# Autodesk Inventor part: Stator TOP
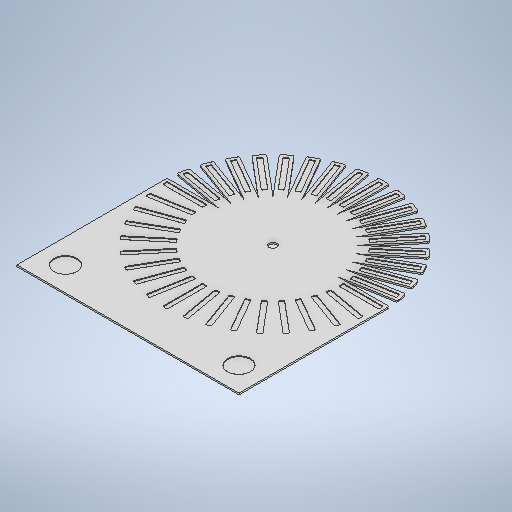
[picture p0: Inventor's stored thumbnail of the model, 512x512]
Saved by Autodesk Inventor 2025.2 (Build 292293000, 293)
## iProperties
Created: 2025-04
Part Number: Stator TOP
Material: Generic
Document SubType Name: Modeling
Designer: bensa
Density: 1 g/cm^3
Appearance: Default
Author: bensa
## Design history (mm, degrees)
sketch "Sketch1"
  geometry: L1 (-143.5, 6.85)-(143.5, 6.85); L2 (145.5, 4.85)-(145.5, -4.85); L3 (143.5, -6.85)-(-143.5, -6.85); L4 (-145.5, -4.85)-(-145.5, 4.85); L5 (-143.406, 6.751)-(145.5, -6.85); L6 (145.5, 6.85)-(-145.5, -6.85); L7 (-6.85, 143.5)-(-6.85, -143.5); L8 (-4.85, -145.5)-(4.85, -145.5); L9 (6.85, -143.5)-(6.85, 143.5); L10 (4.85, 145.5)-(-4.85, 145.5); L11 (-6.85, 145.5)-(6.85, -145.5); L12 (-6.85, -145.5)-(6.85, 145.5); L13 (-140.13, 31.664)-(142.509, -18.173); L14 (144.132, -20.489)-(142.447, -30.042); L15 (140.13, -31.664)-(-142.509, 18.173); L16 (-144.132, 20.489)-(-142.447, 30.042); L17 (-142.1, 32.012)-(142.1, -32.012); L18 (144.479, -18.52)-(-144.479, 18.52); L19 (-142.1, 32.012)-(144.9, 32.012); L20 (-137.189, 42.643)-(132.503, -55.517); L21 (135.066, -54.321)-(138.384, -45.206); L22 (137.189, -42.643)-(-132.503, 55.517); L23 (-135.066, 54.321)-(-138.384, 45.206); L24 (-139.068, 43.327)-(139.068, -43.327); L25 (134.382, -56.201)-(-134.382, 56.201); L26 (-139.068, 43.327)-(147.932, 43.327); L27 (-127.7, 65.818)-(120.85, -77.682); L28 (123.582, -76.95)-(128.432, -68.55); L29 (127.7, -65.818)-(-120.85, 77.682); L30 (-123.582, 76.95)-(-128.432, 68.55); L31 (-129.432, 66.818)-(129.432, -66.818); L32 (122.582, -78.682)-(-120.817, 77.55); L33 (-114.33, 86.993)-(105.524, -97.487); L34 (108.342, -97.241)-(114.577, -89.81); L35 (114.33, -86.993)-(-105.524, 97.487); L36 (-108.342, 97.241)-(-114.577, 89.81); L37 (-115.863, 88.278)-(115.863, -88.278); L38 (107.056, -98.773)-(-105.516, 97.351); L39 (-97.487, 105.524)-(86.993, -114.33); L40 (89.81, -114.577)-(97.241, -108.342); L41 (97.487, -105.524)-(-86.993, 114.33); L42 (-89.81, 114.577)-(-97.241, 108.342); L43 (-98.773, 107.056)-(98.773, -107.056); L44 (87.008, -114.195)-(-88.278, 115.863); L45 (-77.682, 120.85)-(65.818, -127.7); L46 (68.55, -128.432)-(76.95, -123.582); L47 (77.682, -120.85)-(-65.818, 127.7); L48 (-68.55, 128.432)-(-76.95, 123.582); L49 (-78.682, 122.582)-(78.682, -122.582); L50 (66.818, -129.432)-(-66.818, 129.432); L51 (-55.517, 132.503)-(42.643, -137.189); L52 (45.206, -138.384)-(54.321, -135.066); L53 (55.517, -132.503)-(-42.643, 137.189); L54 (-45.206, 138.384)-(-54.321, 135.066); L55 (-56.201, 134.382)-(56.201, -134.382); L56 (43.327, -139.068)-(-43.327, 139.068); L57 (-31.664, 140.13)-(18.173, -142.509); L58 (20.489, -144.132)-(30.042, -142.447); L59 (31.664, -140.13)-(-18.173, 142.509); L60 (-20.489, 144.132)-(-30.042, 142.447); L61 (-32.012, 142.1)-(32.012, -142.1); L62 (18.52, -144.479)-(-18.52, 144.479); L63 (18.173, 142.509)-(-31.664, -140.13); L64 (-30.042, -142.447)-(-20.489, -144.132)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; A1 r 2 centre (113.045, 88.525) between (114.33, 86.993) and (114.577, 89.81); A2 r 2 centre (121.85, 75.95) between (123.582, 76.95) and (120.85, 77.682); A3 r 2 centre (126.7, 67.55) between (127.7, 65.818) and (128.432, 68.55); A4 r 2 centre (133.187, 53.637) between (135.066, 54.321) and (132.503, 55.517); A5 r 2 centre (136.505, 44.522) between (137.189, 42.643) and (138.384, 45.206); A6 r 2 centre (140.478, 29.695) between (142.447, 30.042) and (140.13, 31.664); A7 r 2 centre (142.162, 20.142) between (142.509, 18.173) and (144.132, 20.489); A8 r 2 centre (143.5, 4.85) between (145.5, 4.85) and (143.5, 6.85); A9 r 2 centre (143.5, -4.85) between (143.5, -6.85) and (145.5, -4.85); A10 r 2 centre (142.162, -20.142) between (144.132, -20.489) and (142.509, -18.173); A11 r 2 centre (140.478, -29.695) between (140.13, -31.664) and (142.447, -30.042); A12 r 2 centre (136.505, -44.522) between (138.384, -45.206) and (137.189, -42.643); A13 r 2 centre (133.187, -53.637) between (132.503, -55.517) and (135.066, -54.321); A14 r 2 centre (126.7, -67.55) between (128.432, -68.55) and (127.7, -65.818); A15 r 2 centre (121.85, -75.95) between (120.85, -77.682) and (123.582, -76.95); A16 r 2 centre (113.045, -88.525) between (114.577, -89.81) and (114.33, -86.993); A17 r 2 centre (106.81, -95.955) between (105.524, -97.487) and (108.342, -97.241); A18 r 2 centre (95.955, -106.81) between (97.241, -108.342) and (97.487, -105.524); A19 r 2 centre (75.95, -121.85) between (76.95, -123.582) and (77.682, -120.85); A20 r 2 centre (67.55, -126.7) between (65.818, -127.7) and (68.55, -128.432); A21 r 2 centre (53.637, -133.187) between (54.321, -135.066) and (55.517, -132.503); A22 r 2 centre (44.522, -136.505) between (42.643, -137.189) and (45.206, -138.384); A23 r 2 centre (29.695, -140.478) between (30.042, -142.447) and (31.664, -140.13); A24 r 2 centre (20.142, -142.162) between (18.173, -142.509) and (20.489, -144.132); A25 r 2 centre (4.85, -143.5) between (4.85, -145.5) and (6.85, -143.5); A26 r 2 centre (-4.85, -143.5) between (-6.85, -143.5) and (-4.85, -145.5); A27 r 2 centre (-20.142, -142.162) between (-20.489, -144.132) and (-18.173, -142.509); A28 r 2 centre (-29.695, -140.478) between (-31.664, -140.13) and (-30.042, -142.447); A29 r 2 centre (-44.522, -136.505) between (-45.206, -138.384) and (-42.643, -137.189); A30 r 2 centre (-53.637, -133.187) between (-55.517, -132.503) and (-54.321, -135.066); A31 r 2 centre (-67.55, -126.7) between (-68.55, -128.432) and (-65.818, -127.7); A32 r 2 centre (-75.95, -121.85) between (-77.682, -120.85) and (-76.95, -123.582); A33 r 2 centre (-88.525, -113.045) between (-89.81, -114.577) and (-86.993, -114.33); A34 r 2 centre (-95.955, -106.81) between (-97.487, -105.524) and (-97.241, -108.342); A35 r 2 centre (-106.81, -95.955) between (-108.342, -97.241) and (-105.524, -97.487); A36 r 2 centre (-113.045, -88.525) between (-114.33, -86.993) and (-114.577, -89.81); A37 r 2 centre (-121.85, -75.95) between (-123.582, -76.95) and (-120.85, -77.682); A38 r 2 centre (-126.7, -67.55) between (-127.7, -65.818) and (-128.432, -68.55); A39 r 2 centre (-136.505, -44.522) between (-137.189, -42.643) and (-138.384, -45.206); A40 r 2 centre (-140.478, -29.695) between (-142.447, -30.042) and (-140.13, -31.664); A41 r 2 centre (-142.162, -20.142) between (-142.509, -18.173) and (-144.132, -20.489); A42 r 2 centre (-143.5, -4.85) between (-145.5, -4.85) and (-143.5, -6.85); A43 r 2 centre (-142.162, 20.142) between (-144.132, 20.489) and (-142.509, 18.173); A44 r 2 centre (-140.478, 29.695) between (-140.13, 31.664) and (-142.447, 30.042); A45 r 2 centre (-136.505, 44.522) between (-138.384, 45.206) and (-137.189, 42.643); A46 r 2 centre (-133.187, 53.637) between (-132.503, 55.517) and (-135.066, 54.321); A47 r 2 centre (-126.7, 67.55) between (-128.432, 68.55) and (-127.7, 65.818); A48 r 2 centre (-113.045, 88.525) between (-114.577, 89.81) and (-114.33, 86.993); A49 r 2 centre (-95.955, 106.81) between (-97.241, 108.342) and (-97.487, 105.524); A50 r 2 centre (-88.525, 113.045) between (-86.993, 114.33) and (-89.81, 114.577); A51 r 2 centre (-75.95, 121.85) between (-76.95, 123.582) and (-77.682, 120.85); A52 r 2 centre (-67.55, 126.7) between (-65.818, 127.7) and (-68.55, 128.432); A53 r 2 centre (-53.637, 133.187) between (-54.321, 135.066) and (-55.517, 132.503); A54 r 2 centre (-44.522, 136.505) between (-42.643, 137.189) and (-45.206, 138.384); A55 r 2 centre (-29.695, 140.478) between (-30.042, 142.447) and (-31.664, 140.13); A56 r 2 centre (-20.142, 142.162) between (-18.173, 142.509) and (-20.489, 144.132); A57 r 2 centre (-4.85, 143.5) between (-4.85, 145.5) and (-6.85, 143.5); A58 r 2 centre (4.85, 143.5) between (6.85, 143.5) and (4.85, 145.5); A59 r 2 centre (20.142, 142.162) between (20.489, 144.132) and (18.173, 142.509); A60 r 2 centre (29.695, 140.478) between (31.664, 140.13) and (30.042, 142.447); A61 r 2 centre (44.522, 136.505) between (45.206, 138.384) and (42.643, 137.189); A62 r 2 centre (53.637, 133.187) between (55.517, 132.503) and (54.321, 135.066); A63 r 2 centre (67.55, 126.7) between (68.55, 128.432) and (65.818, 127.7); A64 r 2 centre (75.95, 121.85) between (77.682, 120.85) and (76.95, 123.582)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; 45 further points
  constraints: 220 end point, 158 point on line, 144 point on circle, 144 tangent, 72 centre point, 36 equal radius, 36 parallel, 31 midpoint, 19 perpendicular, 3 horizontal, 2 equal length, 1 vertical
  dimensions: "d1" = 13.7 distance of L6.start L5.end; "d52" = 2 radius of A9 (derived); "d53" = 2 radius of A23 (derived); "d54" = 2 radius of A60 (derived); "d58" = 2 radius of A66 (derived); "d59" = 2 radius of A67 (derived); "d60" = 2 radius of A68 (derived); "d61" = 2 radius of A69 (derived); "d62" = 2 radius of A70 (derived); "d63" = 2 radius of A71 (derived); "d64" = 2 radius of A72 (derived)
sketch "Sketch2"
  geometry: L1 (-145.5, 190)-(-145.5, 0); L2 (-145.5, 0)-(145.5, 0); L3 (145.5, 0)-(145.5, 190); L4 (145.5, 190)-(-145.5, 190); L5 (-145.5, 190)-(145.5, 0); L6 (-145.5, 0)-(145.5, 190); 2 further points
  constraints: 12 end point, 2 midpoint, 2 parallel, 1 perpendicular
extrude "Extrusion1" new body sketch "Sketch1" distance "d65" = 2; taper "d66" = 0 deg
sketch "Sketch4"
  geometry: L1 (142.509, -18.173)-(78.296, -6.85) reference; L2 (64.381, -45.08)-(114.33, -86.993) reference; L3 (42.643, -137.189)-(20.342, -75.917) reference; L4 (18.173, 142.509)-(6.85, 78.296) reference; L5 (2, 141.65)-(-2, 141.65); L6 (31.664, 140.13)-(20.342, 75.917) reference; L7 (45.628, 134.134)-(50.327, 132.423); L8 (20.342, 75.917)-(42.643, 137.189) reference; L9 (68.857, 123.808)-(73.188, 121.308); L10 (-72.557, 121.672)-(-69.093, 123.672); L11 (-65.818, 127.7)-(-33.216, 71.231) reference; L12 (-50.327, 132.423)-(-46.568, 133.792); L13 (-42.643, 137.189)-(-20.342, 75.917) reference; L14 (-26.567, 139.151)-(-22.628, 139.845); L15 (-18.173, 142.509)-(-6.85, 78.296) reference; L16 (89.519, 109.796)-(93.349, 106.582); L17 (45.08, 64.381)-(86.993, 114.33) reference; L18 (106.582, 93.349)-(109.796, 89.519); L19 (121.672, 72.557)-(123.672, 69.093); L20 (71.231, 33.216)-(127.7, 65.818) reference; L21 (132.423, 50.327)-(133.792, 46.568); L22 (139.151, 26.567)-(139.845, 22.628); L23 (75.917, 20.342)-(140.13, 31.664) reference; L24 (141.65, 2)-(141.65, -2); L25 (143.5, -6.85)-(78.296, -6.85) reference; L26 (132.081, -51.266)-(134.134, -45.628); L27 (107.225, -92.583)-(109.796, -89.519); L28 (121.672, -72.557)-(124.172, -68.227); L29 (89.519, -109.796)-(92.583, -107.225); L30 (69.093, -123.672)-(72.557, -121.672); L31 (46.568, -133.792)-(50.327, -132.423); L32 (22.628, -139.845)-(26.567, -139.151); L33 (-2, -141.65)-(2, -141.65); L34 (-26.567, -139.151)-(-22.628, -139.845); L35 (-73.188, -121.308)-(-68.857, -123.808); L36 (-50.327, -132.423)-(-46.568, -133.792); L37 (-92.583, -107.225)-(-89.519, -109.796); L38 (-109.796, -89.519)-(-107.225, -92.583); L39 (-123.672, -69.093)-(-121.672, -72.557); L40 (-133.792, -46.568)-(-132.423, -50.327); L41 (-141.65, -2)-(-141.65, 2); L42 (-139.845, 22.628)-(-139.151, 26.567); L43 (-133.792, 46.568)-(-132.423, 50.327); L44 (-124.172, 68.227)-(-121.172, 73.423); L45 (-109.796, 89.519)-(-107.225, 92.583); L46 (-89.519, 109.796)-(-92.583, 107.225); L47 (-27.552, 138.977)-(-21.643, 140.019); L48 (-21.469, 139.034)-(-12.735, 89.498); L49 (-13.546, 88.34)-(-17.485, 87.645); L50 (-18.644, 88.456)-(-27.378, 137.992); L51 (-3, 141.65)-(3, 141.65); L52 (3, 140.65)-(3, 90.35); L53 (2, 89.35)-(-2, 89.35); L54 (-3, 90.35)-(-3, 140.65); L55 (22.628, 139.845)-(27.552, 138.977); L56 (21.643, 140.019)-(26.567, 139.151); L57 (27.378, 137.992)-(18.644, 88.456); L58 (17.485, 87.645)-(13.546, 88.34); L59 (12.735, 89.498)-(21.469, 139.034); L60 (46.568, 133.792)-(51.266, 132.081); L61 (50.924, 131.142)-(33.721, 83.875); L62 (32.439, 83.277)-(28.68, 84.646); L63 (28.082, 85.927)-(45.286, 133.194); L64 (67.991, 124.308)-(72.321, 121.808)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; A1 r 1 centre (-138.166, 26.393) between (-137.992, 27.378) and (-139.151, 26.567); A2 r 1 centre (-88.63, 17.659) between (-87.645, 17.485) and (-88.456, 18.644); A3 r 1 centre (-89.325, 13.719) between (-89.498, 12.735) and (-88.34, 13.546); A4 r 1 centre (-138.861, 22.454) between (-139.845, 22.628) and (-139.034, 21.469); A5 r 1 centre (-132.852, 46.226) between (-133.792, 46.568) and (-133.194, 45.286); A6 r 1 centre (-131.484, 49.985) between (-131.142, 50.924) and (-132.423, 50.327); A7 r 1 centre (-84.217, 32.781) between (-83.277, 32.439) and (-83.875, 33.721); A8 r 1 centre (-85.585, 29.022) between (-85.927, 28.082) and (-84.646, 28.68); A9 r 1 centre (-79.245, 43.443) between (-79.745, 42.577) and (-78.379, 42.943); A10 r 1 centre (-122.806, 68.593) between (-123.672, 69.093) and (-123.306, 67.727); A11 r 1 centre (-120.806, 72.057) between (-120.306, 72.923) and (-121.672, 72.557); A12 r 1 centre (-77.245, 46.907) between (-76.379, 46.407) and (-76.745, 47.773); A13 r 1 centre (-109.03, 88.876) between (-109.796, 89.519) and (-109.673, 88.11); A14 r 1 centre (-106.459, 91.94) between (-105.816, 92.706) and (-107.225, 92.583); A15 r 1 centre (-67.927, 59.608) between (-67.16, 58.965) and (-67.284, 60.374); A16 r 1 centre (-70.498, 56.544) between (-71.14, 55.778) and (-69.732, 55.901); A17 r 1 centre (-91.94, 106.459) between (-92.583, 107.225) and (-92.706, 105.816); A18 r 1 centre (-56.544, 70.498) between (-55.901, 69.732) and (-55.778, 71.14); A19 r 1 centre (-56.544, 70.498) between (-55.901, 69.732) and (-55.778, 71.14); A20 r 1 centre (-59.608, 67.927) between (-60.374, 67.284) and (-58.965, 67.16); A21 r 1 centre (-88.876, 109.03) between (-88.11, 109.673) and (-89.519, 109.796); A22 r 1 centre (-72.057, 120.806) between (-72.557, 121.672) and (-72.923, 120.306); A23 r 1 centre (-68.593, 122.806) between (-67.727, 123.306) and (-69.093, 123.672); A24 r 1 centre (-43.443, 79.245) between (-42.943, 78.379) and (-42.577, 79.745); A25 r 1 centre (-46.907, 77.245) between (-47.773, 76.745) and (-46.407, 76.379); A26 r 1 centre (-49.985, 131.484) between (-50.327, 132.423) and (-50.924, 131.142); A27 r 1 centre (-46.226, 132.852) between (-45.286, 133.194) and (-46.568, 133.792); A28 r 1 centre (-29.022, 85.585) between (-28.68, 84.646) and (-28.082, 85.927); A29 r 1 centre (-32.781, 84.217) between (-33.721, 83.875) and (-32.439, 83.277); A30 r 1 centre (-17.659, 88.63) between (-18.644, 88.456) and (-17.485, 87.645); A31 r 1 centre (-26.393, 138.166) between (-26.567, 139.151) and (-27.378, 137.992); A32 r 1 centre (-22.454, 138.861) between (-21.469, 139.034) and (-22.628, 139.845); A33 r 1 centre (-13.719, 89.325) between (-13.546, 88.34) and (-12.735, 89.498); A34 r 1 centre (-2, 140.65) between (-2, 141.65) and (-3, 140.65); A35 r 1 centre (2, 140.65) between (3, 140.65) and (2, 141.65); A36 r 1 centre (2, 90.35) between (2, 89.35) and (3, 90.35); A37 r 1 centre (-2, 90.35) between (-3, 90.35) and (-2, 89.35); A38 r 1 centre (22.454, 138.861) between (22.628, 139.845) and (21.469, 139.034); A39 r 1 centre (26.393, 138.166) between (27.378, 137.992) and (26.567, 139.151); A40 r 1 centre (13.719, 89.325) between (12.735, 89.498) and (13.546, 88.34); A41 r 1 centre (17.659, 88.63) between (17.485, 87.645) and (18.644, 88.456); A42 r 1 centre (29.022, 85.585) between (28.082, 85.927) and (28.68, 84.646); A43 r 1 centre (46.226, 132.852) between (46.568, 133.792) and (45.286, 133.194); A44 r 1 centre (49.985, 131.484) between (50.924, 131.142) and (50.327, 132.423); A45 r 1 centre (32.781, 84.217) between (32.439, 83.277) and (33.721, 83.875); A46 r 1 centre (43.207, 79.381) between (42.341, 79.881) and (42.707, 78.515); A47 r 1 centre (68.357, 122.942) between (68.857, 123.808) and (67.491, 123.442); A48 r 1 centre (71.821, 120.942) between (72.688, 120.442) and (72.321, 121.808); A49 r 1 centre (46.671, 77.381) between (46.171, 76.515) and (47.538, 76.881); A50 r 1 centre (56.544, 70.498) between (55.778, 71.14) and (55.901, 69.732); A51 r 1 centre (88.876, 109.03) between (89.519, 109.796) and (88.11, 109.673); A52 r 1 centre (91.94, 106.459) between (92.706, 105.816) and (92.583, 107.225); A53 r 1 centre (59.608, 67.927) between (58.965, 67.16) and (60.374, 67.284); A54 r 1 centre (67.927, 59.608) between (67.284, 60.374) and (67.16, 58.965); A55 r 1 centre (106.459, 91.94) between (107.225, 92.583) and (105.816, 92.706); A56 r 1 centre (109.03, 88.876) between (109.673, 88.11) and (109.796, 89.519); A57 r 1 centre (70.498, 56.544) between (69.732, 55.901) and (71.14, 55.778); A58 r 1 centre (77.245, 46.907) between (76.745, 47.773) and (76.379, 46.407); A59 r 1 centre (120.806, 72.057) between (121.672, 72.557) and (120.306, 72.923); A60 r 1 centre (122.806, 68.593) between (123.306, 67.727) and (123.672, 69.093); A61 r 1 centre (79.245, 43.443) between (78.379, 42.943) and (79.745, 42.577); A62 r 1 centre (84.217, 32.781) between (83.875, 33.721) and (83.277, 32.439); A63 r 1 centre (131.484, 49.985) between (132.423, 50.327) and (131.142, 50.924); A64 r 1 centre (132.852, 46.226) between (133.194, 45.286) and (133.792, 46.568)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; 15 further points
  constraints: 360 end point, 290 point on circle, 290 tangent, 146 point on line, 145 centre point, 141 equal radius, 73 parallel, 45 perpendicular, 31 collinear, 2 horizontal, 1 vertical
  dimensions: "d256" = 52.3 distance of L163.end point (-89.35, 3); "d264" = 1 radius of A1 (derived); "d265" = 1 radius of A34 (derived); "d266" = 1 radius of A94 (derived); "d267" = 1 radius of A118 (derived)
extrude "Extrusion2" join sketch "Sketch2" distance "d268" = 2; taper "d269" = 0 deg
extrude "Extrusion3" cut sketch "Sketch4" distance "d270" = 1; taper "d271" = 0 deg
sketch "Sketch5"
  geometry: L1 (-145.5, 4.85)-(-145.5, -190) reference; L2 (-145.5, -190)-(-100.5, -190); L3 (-145.5, -190)-(145.5, -190) reference; L4 (145.5, -190)-(190.5, -190); C1 r 15 at (-113.68, -158.18); C2 r 15 at (113.68, -158.18); 1 further point
  constraints: 4 end point, 2 centre point, 2 horizontal
extrude "Extrusion4" cut sketch "Sketch5" distance "d278" = 1; taper "d279" = 0 deg
sketch "Sketch6"
  geometry: C1 r 5 at (0, 0); 1 further point
  constraints: 1 centre point, 1 coincident
  dimensions: "d280" = 10 diameter of C1
extrude "Extrusion5" cut sketch "Sketch6" distance "d281" = 2; taper "d282" = 0 deg
body "Solid1"
